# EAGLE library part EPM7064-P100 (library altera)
EPM7064 MAX 7000 family
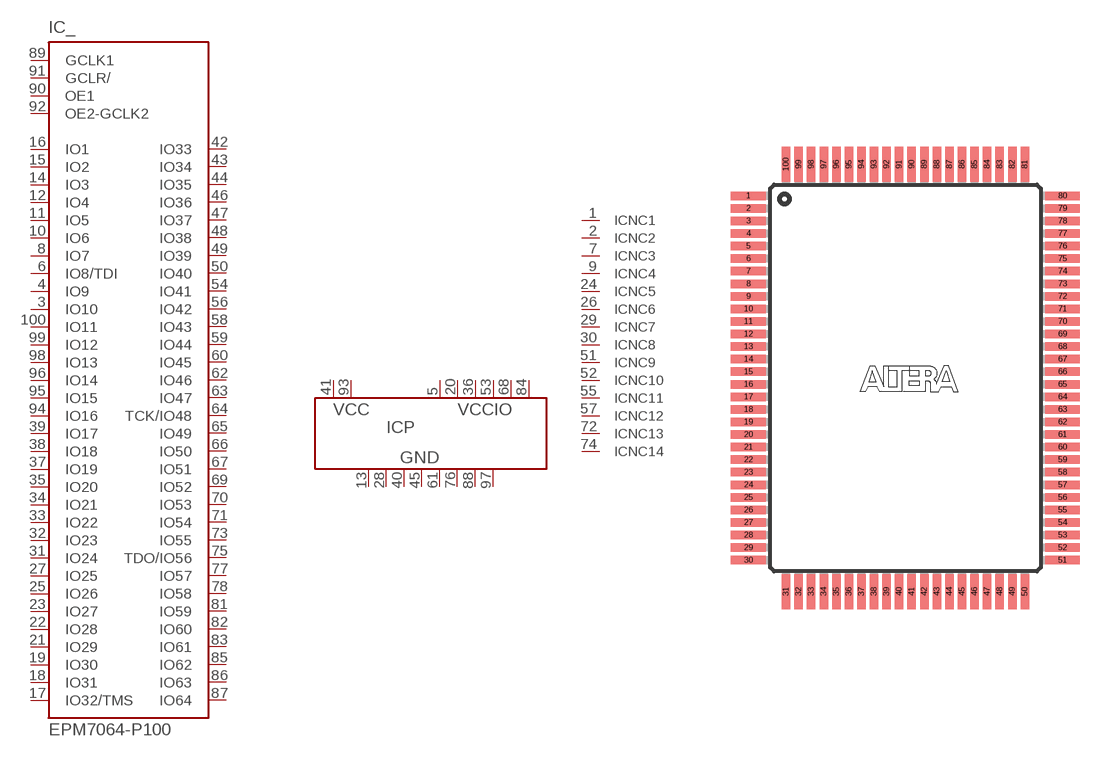
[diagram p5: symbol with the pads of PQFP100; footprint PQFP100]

Designator prefix IC; gates _=EPM7064S P=PWR8-2-6 NC1=NC NC2=NC NC3=NC NC4=NC NC5=NC NC6=NC NC7=NC NC8=NC NC9=NC NC10=NC NC11=NC NC12=NC NC13=NC NC14=NC NC15=NC NC16=NC

## EPM7064-P100 (MPN: EPM7064STI100-7N; OC_FARNELL: 1549426; OC_NEWARK: 51R9650)  [PQFP100]
1  NC1:NC  nc
2  NC2:NC  nc
3  _:IO10
4  _:IO9
5  P:VCCIO  pwr
6  _:IO8/TDI
7  NC3:NC  nc
8  _:IO7
9  NC4:NC  nc
10  _:IO6
11  _:IO5
12  _:IO4
13  P:GND  pwr
14  _:IO3
15  _:IO2
16  _:IO1
17  _:IO32/TMS
18  _:IO31
19  _:IO30
20  P:VCCIO  pwr
21  _:IO29
22  _:IO28
23  _:IO27
24  NC5:NC  nc
25  _:IO26
26  NC6:NC  nc
27  _:IO25
28  P:GND  pwr
29  NC7:NC  nc
30  NC8:NC  nc
31  _:IO24
32  _:IO23
33  _:IO22
34  _:IO21
35  _:IO20
36  P:VCCIO  pwr
37  _:IO19
38  _:IO18
39  _:IO17
40  P:GND  pwr
41  P:VCC  pwr
42  _:IO33
43  _:IO34
44  _:IO35
45  P:GND  pwr
46  _:IO36
47  _:IO37
48  _:IO38
49  _:IO39
50  _:IO40
51  NC9:NC  nc
52  NC10:NC  nc
53  P:VCCIO  pwr
54  _:IO41
55  NC11:NC  nc
56  _:IO42
57  NC12:NC  nc
58  _:IO43
59  _:IO44
60  _:IO45
61  P:GND  pwr
62  _:IO46
63  _:IO47
64  _:TCK/IO48
65  _:IO49
66  _:IO50
67  _:IO51
68  P:VCCIO  pwr
69  _:IO52
70  _:IO53
71  _:IO54
72  NC13:NC  nc
73  _:IO55
74  NC14:NC  nc
75  _:TDO/IO56
76  P:GND  pwr
77  _:IO57
78  _:IO58
79  NC15:NC  nc
80  NC16:NC  nc
81  _:IO59
82  _:IO60
83  _:IO61
84  P:VCCIO  pwr
85  _:IO62
86  _:IO63
87  _:IO64
88  P:GND  pwr
89  _:GCLK1  in
90  _:OE1  in
91  _:GCLR/  in
92  _:OE2-GCLK2  in
93  P:VCC  pwr
94  _:IO16
95  _:IO15
96  _:IO14
97  P:GND  pwr
98  _:IO13
99  _:IO12
100  _:IO11

## Footprint PQFP100 (pad centres in mm)
Plastic Quad Flat Pack
smd 1.8 x 0.44: 1 -8.125,9.425; 2 -8.125,8.775; 3 -8.125,8.125; 4 -8.125,7.475; 5 -8.125,6.825; 6 -8.125,6.175; 7 -8.125,5.525; 8 -8.125,4.875; 9 -8.125,4.225; 10 -8.125,3.575; 11 -8.125,2.925; 12 -8.125,2.275; 13 -8.125,1.625; 14 -8.125,0.975; 15 -8.125,0.325; 16 -8.125,-0.325; 17 -8.125,-0.975; 18 -8.125,-1.625; 19 -8.125,-2.275; 20 -8.125,-2.925; 21 -8.125,-3.575; 22 -8.125,-4.225; 23 -8.125,-4.875; 24 -8.125,-5.525; 25 -8.125,-6.175; 26 -8.125,-6.825; 27 -8.125,-7.475; 28 -8.125,-8.125; 29 -8.125,-8.775; 30 -8.125,-9.425; 51 8.125,-9.425; 52 8.125,-8.775; 53 8.125,-8.125; 54 8.125,-7.475; 55 8.125,-6.825; 56 8.125,-6.175; 57 8.125,-5.525; 58 8.125,-4.875; 59 8.125,-4.225; 60 8.125,-3.575; 61 8.125,-2.925; 62 8.125,-2.275; 63 8.125,-1.625; 64 8.125,-0.975; 65 8.125,-0.325; 66 8.125,0.325; 67 8.125,0.975; 68 8.125,1.625; 69 8.125,2.275; 70 8.125,2.925; 71 8.125,3.575; 72 8.125,4.225; 73 8.125,4.875; 74 8.125,5.525; 75 8.125,6.175; 76 8.125,6.825; 77 8.125,7.475; 78 8.125,8.125; 79 8.125,8.775; 80 8.125,9.425
smd 0.44 x 1.8: 31 -6.175,-11.05; 32 -5.525,-11.05; 33 -4.875,-11.05; 34 -4.225,-11.05; 35 -3.575,-11.05; 36 -2.925,-11.05; 37 -2.275,-11.05; 38 -1.625,-11.05; 39 -0.975,-11.05; 40 -0.325,-11.05; 41 0.325,-11.05; 42 0.975,-11.05; 43 1.625,-11.05; 44 2.275,-11.05; 45 2.925,-11.05; 46 3.575,-11.05; 47 4.225,-11.05; 48 4.875,-11.05; 49 5.525,-11.05; 50 6.175,-11.05; 81 6.175,11.05; 82 5.525,11.05; 83 4.875,11.05; 84 4.225,11.05; 85 3.575,11.05; 86 2.925,11.05; 87 2.275,11.05; 88 1.625,11.05; 89 0.975,11.05; 90 0.325,11.05; 91 -0.325,11.05; 92 -0.975,11.05; 93 -1.625,11.05; 94 -2.275,11.05; 95 -2.925,11.05; 96 -3.575,11.05; 97 -4.225,11.05; 98 -4.875,11.05; 99 -5.525,11.05; 100 -6.175,11.05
